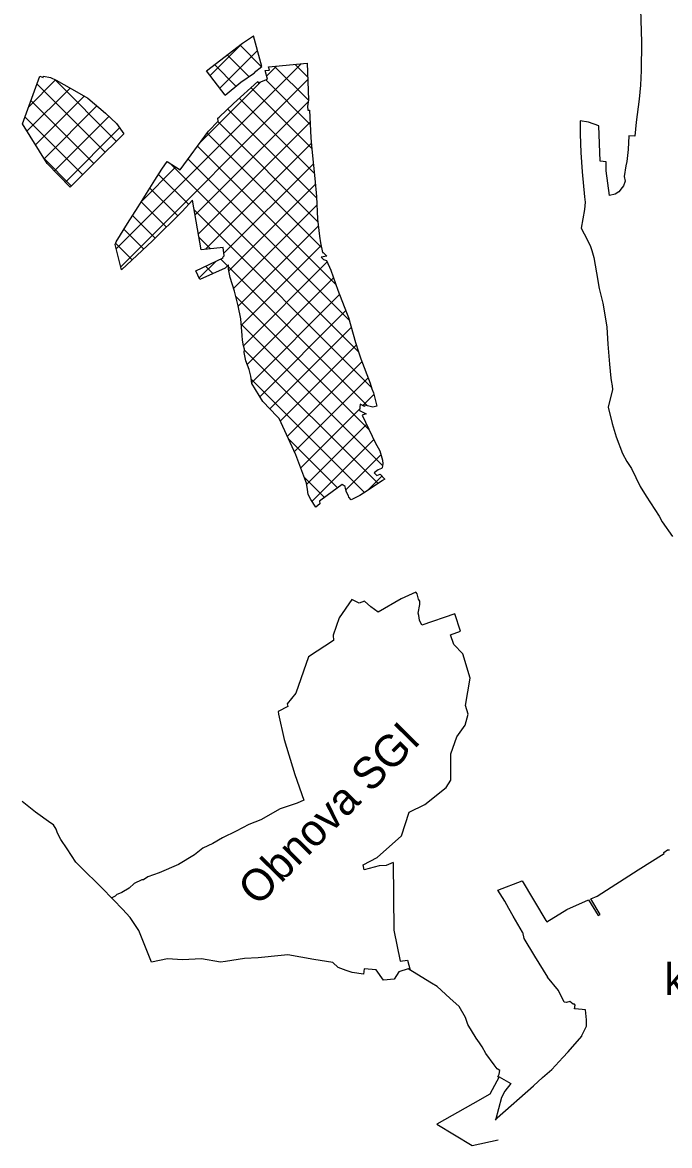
# Model space of a CAD drawing. Extents: x -550720 to -543671, y -1204329 to -1198338.
# Drawn here: x -547935 to -545892, y -1204329 to -1200786 of the extents above; entities that cross this region are included whole.
import ezdxf

# ---------------------------------------------------------------- set-up
doc = ezdxf.new("R2010")
doc.units = 0
for name, color, linetype in [('Ob šetřený', 7, 'Continuous'), ('obnova SGI', 7, 'Continuous'), ('Text kú', 7, 'Continuous'), ('šrafy', 7, 'Continuous')]:
    doc.layers.add(name, color=color, linetype=linetype)

msp = doc.modelspace()

# ---------------------------------------------------------------- linework, layer by layer
at = {"layer": 'Ob šetřený'}
for p, q in [((-545983.3, -1200744.3), (-545980.6, -1200848)), ((-547354, -1200938.3), (-547239.8, -1200851.8)), ((-547239.8, -1200851.8), (-547205.7, -1200827.7)), ((-547178.8, -1200925), (-547205.7, -1200827.7)), ((-545980.6, -1200848), (-545981.5, -1200937.8)), ((-547202.9, -1200943.6), (-547178.8, -1200925)), ((-547157.8, -1200926.2), (-547035.7, -1200914.4)), ((-547035.7, -1200914.4), (-547031.4, -1201029.9)), ((-547934.3, -1201106.2), (-547879.4, -1200955.7)), ((-547879.4, -1200955.7), (-547869.7, -1200960)), ((-547869.7, -1200960), (-547868.4, -1200955)), ((-547868.4, -1200955), (-547846.7, -1200959.7)), ((-547846.7, -1200959.7), (-547828.7, -1200967.9)), ((-547295.3, -1201015), (-547354, -1200938.3)), ((-547245.8, -1200974.7), (-547202.6, -1200944.7)), ((-547202.6, -1200944.7), (-547202.9, -1200943.6)), ((-547168.7, -1200937.3), (-547154.9, -1200936.1)), ((-547160.8, -1200965.4), (-547168.7, -1200937.3)), ((-547154.9, -1200936.1), (-547157.8, -1200926.2)), ((-545981.5, -1200937.8), (-545983.1, -1200984.2)), ((-547828.7, -1200967.9), (-547755.2, -1201009.3)), ((-547295.3, -1201015), (-547245.8, -1200974.7)), ((-547268.2, -1201041.3), (-547192, -1200971.8)), ((-547192, -1200971.8), (-547190.1, -1200976.5)), ((-547190.1, -1200976.5), (-547160.8, -1200965.4)), ((-545983.1, -1200984.2), (-545988, -1201028)), ((-547755.2, -1201009.3), (-547728.1, -1201025)), ((-547728.1, -1201025), (-547673, -1201071.9)), ((-547031.4, -1201029.9), (-547034.5, -1201051.6)), ((-545988, -1201028), (-545996.8, -1201100.7)), ((-547313.2, -1201084.3), (-547268.2, -1201041.3)), ((-547034.5, -1201051.6), (-547034.1, -1201062.9)), ((-547034.1, -1201062.9), (-547028.1, -1201062.4)), ((-547028.1, -1201062.4), (-547024.6, -1201149.7)), ((-547673, -1201071.9), (-547638.2, -1201105.1)), ((-547347.2, -1201129.3), (-547317.3, -1201097.1)), ((-547317.8, -1201087.9), (-547313.2, -1201084.3)), ((-547317.3, -1201097.1), (-547317.8, -1201087.9)), ((-546173.6, -1201096.4), (-546173.7, -1201138.4)), ((-546147.3, -1201100.8), (-546173.6, -1201096.4)), ((-546115.5, -1201111.9), (-546147.3, -1201100.8)), ((-545996.8, -1201100.7), (-546001.8, -1201144.2)), ((-547856.4, -1201231.4), (-547934.3, -1201106.2)), ((-547614.5, -1201136.8), (-547703.2, -1201224.6)), ((-547638.2, -1201105.1), (-547614.5, -1201136.8)), ((-547437.2, -1201251.1), (-547347.2, -1201129.3)), ((-546111.1, -1201223.8), (-546115.5, -1201111.9)), ((-547024.6, -1201149.7), (-547021, -1201186.1)), ((-546173.7, -1201138.4), (-546171.7, -1201196.6)), ((-546020.7, -1201143.8), (-546023, -1201187.1)), ((-546001.8, -1201144.2), (-546020.7, -1201143.8)), ((-547021, -1201186.1), (-547011.2, -1201277.8)), ((-546171.7, -1201196.6), (-546167.9, -1201257.2)), ((-546023, -1201187.1), (-546027, -1201224.9)), ((-547783.7, -1201305.8), (-547856.4, -1201231.4)), ((-547703.2, -1201224.6), (-547783.7, -1201305.8)), ((-547494.2, -1201248.5), (-547478.1, -1201224.7)), ((-547478.1, -1201224.7), (-547437.2, -1201251.1)), ((-546092.4, -1201225.8), (-546111.1, -1201223.8)), ((-546091.6, -1201253.6), (-546092.4, -1201225.8)), ((-546029.6, -1201238.4), (-546034.8, -1201271.5)), ((-546027, -1201224.9), (-546029.6, -1201238.4)), ((-547516.8, -1201283.4), (-547494.2, -1201248.5)), ((-547011.2, -1201277.8), (-547006.5, -1201335.2)), ((-546167.9, -1201257.2), (-546160.6, -1201335.9)), ((-546081.3, -1201331.6), (-546091.6, -1201253.6)), ((-546034.8, -1201271.5), (-546032, -1201286.6)), ((-547569.7, -1201367.4), (-547516.8, -1201283.4)), ((-546041.1, -1201306.9), (-546051.5, -1201320)), ((-546037.5, -1201300.9), (-546041.1, -1201306.9)), ((-546032, -1201286.6), (-546037.5, -1201300.9)), ((-547397.4, -1201346.4), (-547430.2, -1201382.5)), ((-547370.7, -1201503), (-547397.4, -1201346.4)), ((-547006.5, -1201335.2), (-547002.9, -1201406.5)), ((-546160.6, -1201335.9), (-546157.8, -1201353.1)), ((-546063.4, -1201327.6), (-546081.3, -1201331.6)), ((-546051.5, -1201320), (-546063.4, -1201327.6)), ((-547602.8, -1201419.8), (-547569.7, -1201367.4)), ((-547430.2, -1201382.5), (-547524.1, -1201475.3)), ((-546160.8, -1201376.4), (-546171, -1201435)), ((-546157.8, -1201353.1), (-546160.8, -1201376.4)), ((-547639.1, -1201478.2), (-547602.8, -1201419.8)), ((-547002.9, -1201406.5), (-546996.7, -1201460.6)), ((-546171, -1201435), (-546161.8, -1201452.8)), ((-546161.8, -1201452.8), (-546142, -1201490.1)), ((-547642.3, -1201485.9), (-547639.1, -1201478.2)), ((-547622.2, -1201566.6), (-547642.3, -1201485.9)), ((-547524.1, -1201475.3), (-547622.2, -1201566.6)), ((-546996.7, -1201460.6), (-546994.3, -1201481.4)), ((-546994.3, -1201481.4), (-546987.6, -1201511.9)), ((-546142, -1201490.1), (-546136.7, -1201505.5)), ((-547301.2, -1201495.9), (-547370.7, -1201503)), ((-547302.3, -1201526.2), (-547297.8, -1201522.6)), ((-547301.5, -1201528), (-547302.3, -1201526.2)), ((-547297.8, -1201522.6), (-547301.2, -1201495.9)), ((-546973.6, -1201523.6), (-546992, -1201526.1)), ((-546992, -1201526.1), (-546984, -1201533.9)), ((-546987.6, -1201511.9), (-546985.1, -1201511.6)), ((-546985.1, -1201511.6), (-546973.6, -1201523.6)), ((-546136.7, -1201505.5), (-546130.6, -1201527.1)), ((-546130.6, -1201527.1), (-546123, -1201575.9)), ((-547386.9, -1201569.9), (-547301.5, -1201528)), ((-547294.3, -1201561.4), (-547374.6, -1201596.4)), ((-547284.3, -1201550.5), (-547294.3, -1201561.4)), ((-547284.7, -1201564.4), (-547284.3, -1201550.5)), ((-546984, -1201533.9), (-546974.7, -1201537.2)), ((-546974.7, -1201537.2), (-546960.7, -1201567.7)), ((-547374.6, -1201596.4), (-547386.9, -1201569.9)), ((-547279.3, -1201590.3), (-547284.7, -1201564.4)), ((-547265.5, -1201633.4), (-547279.3, -1201590.3)), ((-546960.7, -1201567.7), (-546938.6, -1201630.7)), ((-546123, -1201575.9), (-546113.6, -1201625.4)), ((-547253.9, -1201679.5), (-547265.5, -1201633.4)), ((-546938.6, -1201630.7), (-546911.4, -1201701.3)), ((-546113.6, -1201625.4), (-546102.7, -1201671.6)), ((-547245.7, -1201720.7), (-547253.9, -1201679.5)), ((-546911.4, -1201701.3), (-546905.7, -1201716.6)), ((-546102.7, -1201671.6), (-546094.1, -1201720.6)), ((-547240.8, -1201774), (-547245.7, -1201720.7)), ((-546905.7, -1201716.6), (-546882.8, -1201795.3)), ((-546094.1, -1201720.6), (-546090.3, -1201746.7)), ((-547239.9, -1201788.3), (-547240.8, -1201774)), ((-546090.3, -1201746.7), (-546086.5, -1201801.1)), ((-547237.1, -1201806.5), (-547239.9, -1201788.3)), ((-547234.1, -1201816.5), (-547237.1, -1201806.5)), ((-546882.8, -1201795.3), (-546873.7, -1201824.6)), ((-546086.5, -1201801.1), (-546081.4, -1201864)), ((-547234.7, -1201827.2), (-547234.1, -1201816.5)), ((-547229.3, -1201853.4), (-547234.7, -1201827.2)), ((-546873.7, -1201824.6), (-546866.2, -1201847.2)), ((-547219.2, -1201880.6), (-547229.3, -1201853.4)), ((-547214.1, -1201901.7), (-547219.2, -1201880.6)), ((-546866.2, -1201847.2), (-546836.6, -1201923.6)), ((-546081.4, -1201864), (-546076.9, -1201908.3)), ((-547210.6, -1201925), (-547214.1, -1201901.7)), ((-546076.9, -1201908.3), (-546076.1, -1201915.6)), ((-546076.1, -1201915.6), (-546072.6, -1201931.9)), ((-547176.2, -1201981.8), (-547210.6, -1201925)), ((-546836.6, -1201923.6), (-546831.6, -1201941.6)), ((-546831.6, -1201941.6), (-546826.7, -1201954.5)), ((-546072.3, -1201943.8), (-546085.7, -1201999.3)), ((-546072.6, -1201931.9), (-546072.3, -1201943.8)), ((-547130.6, -1202029.1), (-547176.2, -1201981.8)), ((-546826.7, -1201954.5), (-546818.7, -1201983.9)), ((-546818.7, -1201983.9), (-546815.8, -1201996.2)), ((-546868.4, -1201990), (-546870.5, -1202009.9)), ((-546870.5, -1202009.9), (-546849.8, -1202020.9)), ((-546854.4, -1201997.6), (-546868.4, -1201990)), ((-546849.8, -1202020.9), (-546862.8, -1202024.3)), ((-546854, -1201992.9), (-546854.4, -1201997.6)), ((-546828.6, -1201999.4), (-546854, -1201992.9)), ((-546815.8, -1201996.2), (-546828.6, -1201999.4)), ((-546085.7, -1201999.3), (-546073, -1202051.3)), ((-547124.8, -1202035.2), (-547130.6, -1202029.1)), ((-547072.2, -1202150.2), (-547124.8, -1202035.2)), ((-546862.8, -1202024.3), (-546830.4, -1202091.4)), ((-546073, -1202051.3), (-546060.3, -1202093.6)), ((-546830.4, -1202091.4), (-546821.6, -1202110.7)), ((-546060.3, -1202093.6), (-546039.9, -1202145.8)), ((-546821.6, -1202110.7), (-546806.7, -1202136.8)), ((-547046.2, -1202217.2), (-547072.2, -1202150.2)), ((-546806.7, -1202136.8), (-546798.2, -1202166.8)), ((-546039.9, -1202145.8), (-546027.2, -1202171.2)), ((-546812.1, -1202197.7), (-546824.1, -1202206.6)), ((-546801.5, -1202193.4), (-546812.1, -1202197.7)), ((-546799.5, -1202191.1), (-546801.5, -1202193.4)), ((-546797.3, -1202178.6), (-546799.5, -1202191.1)), ((-546798.2, -1202166.8), (-546797.3, -1202178.6)), ((-546027.2, -1202171.2), (-546011.8, -1202193.5)), ((-546011.8, -1202193.5), (-545984.6, -1202249.3)), ((-547037.7, -1202239.5), (-547046.2, -1202217.2)), ((-546797.7, -1202231.1), (-546846.1, -1202263.2)), ((-546824.1, -1202206.6), (-546815.8, -1202214.9)), ((-546815.8, -1202214.9), (-546805.4, -1202210.6)), ((-546805.4, -1202210.6), (-546791.1, -1202226.7)), ((-546791.1, -1202226.7), (-546797.7, -1202231.1)), ((-547034.9, -1202259.3), (-547037.7, -1202239.5)), ((-547032.4, -1202275.4), (-547034.9, -1202259.3)), ((-546925.4, -1202244), (-546972.5, -1202277.7)), ((-546915.6, -1202250), (-546925.4, -1202244)), ((-546914.9, -1202255.9), (-546915.6, -1202250)), ((-546911.7, -1202267.7), (-546914.9, -1202255.9)), ((-546905.6, -1202278.9), (-546911.7, -1202267.7)), ((-546846.1, -1202263.2), (-546870, -1202277.8)), ((-545984.6, -1202249.3), (-545965.7, -1202280.5)), ((-547024.7, -1202290.4), (-547032.4, -1202275.4)), ((-547008.2, -1202315), (-547024.7, -1202290.4)), ((-546995.5, -1202305), (-547008.2, -1202315)), ((-546972.5, -1202277.7), (-546996.6, -1202296.4)), ((-546996.6, -1202296.4), (-546995.5, -1202305)), ((-546904.8, -1202283.9), (-546905.6, -1202278.9)), ((-546896.5, -1202291.4), (-546904.8, -1202283.9)), ((-546870, -1202277.8), (-546896.5, -1202291.4)), ((-545965.7, -1202280.5), (-545924.5, -1202342.9)), ((-545924.5, -1202342.9), (-545915.6, -1202361)), ((-545915.6, -1202361), (-545882.3, -1202408)), ((-547893.1, -1203276.8), (-547935.2, -1203243.5)), ((-547845, -1203311.5), (-547893.1, -1203276.8)), ((-547836.9, -1203317), (-547845, -1203311.5)), ((-547827.8, -1203330.8), (-547836.9, -1203317)), ((-547824.3, -1203343.3), (-547827.8, -1203330.8)), ((-547813.9, -1203363.5), (-547824.3, -1203343.3)), ((-547794, -1203393.1), (-547813.9, -1203363.5)), ((-547766.1, -1203434.8), (-547794, -1203393.1)), ((-545909.8, -1203404.7), (-545898.5, -1203395.6)), ((-545909.3, -1203407.6), (-545909.8, -1203404.7)), ((-545898.5, -1203395.6), (-545891.9, -1203396)), ((-547750.1, -1203450.6), (-547766.1, -1203434.8)), ((-545991.3, -1203459.5), (-545909.3, -1203407.6)), ((-547686.1, -1203514.1), (-547750.1, -1203450.6)), ((-546120.6, -1203542.4), (-545991.3, -1203459.5)), ((-546433.5, -1203523), (-546357.3, -1203493.6)), ((-546357.3, -1203493.6), (-546282.2, -1203619.3)), ((-547646.8, -1203553.2), (-547686.1, -1203514.1)), ((-546411.6, -1203558.3), (-546433.5, -1203523)), ((-546140.8, -1203550.3), (-546120.6, -1203542.4)), ((-547619.3, -1203583.3), (-547646.8, -1203553.2)), ((-546399.5, -1203581.5), (-546411.6, -1203558.3)), ((-546385.7, -1203605.2), (-546399.5, -1203581.5)), ((-546215.7, -1203583.9), (-546147.3, -1203553.2)), ((-546147.3, -1203553.2), (-546117.3, -1203603.3)), ((-546111.2, -1203599.7), (-546140.8, -1203550.3)), ((-547595, -1203609.7), (-547619.3, -1203583.3)), ((-547567.3, -1203649.9), (-547595, -1203609.7)), ((-546356, -1203656.2), (-546385.7, -1203605.2)), ((-546279.4, -1203623.5), (-546215.7, -1203583.9)), ((-546117.3, -1203603.3), (-546111.2, -1203599.7)), ((-547527.5, -1203749.9), (-547567.3, -1203649.9)), ((-546282.2, -1203619.3), (-546279.4, -1203623.5)), ((-546356, -1203656.2), (-546351.8, -1203676.1)), ((-546351.8, -1203676.1), (-546318.5, -1203730.9)), ((-547476.6, -1203740.3), (-547527.5, -1203749.9)), ((-547429.8, -1203742.5), (-547476.6, -1203740.3)), ((-547369.7, -1203739.6), (-547429.8, -1203742.5)), ((-547309.9, -1203750.6), (-547369.7, -1203739.6)), ((-547294.2, -1203747.9), (-547309.9, -1203750.6)), ((-547233.9, -1203738.4), (-547294.2, -1203747.9)), ((-547190.1, -1203736.3), (-547233.9, -1203738.4)), ((-547117.7, -1203728.8), (-547190.1, -1203736.3)), ((-547096.6, -1203727.3), (-547117.7, -1203728.8)), ((-547015.2, -1203741.7), (-547096.6, -1203727.3)), ((-546955, -1203751.2), (-547015.2, -1203741.7)), ((-546938, -1203767), (-546955, -1203751.2)), ((-546318.5, -1203730.9), (-546277.1, -1203798.1)), ((-546912.9, -1203776.6), (-546938, -1203767)), ((-546893.6, -1203782.8), (-546912.9, -1203776.6)), ((-546858.1, -1203787.9), (-546893.6, -1203782.8)), ((-546856, -1203771.5), (-546858.1, -1203787.9)), ((-546818.4, -1203774.8), (-546856, -1203771.5)), ((-546794.9, -1203806.7), (-546818.4, -1203774.8)), ((-546746.6, -1203780.7), (-546760.9, -1203803.7)), ((-546717.4, -1203771.5), (-546746.6, -1203780.7)), ((-546643.5, -1203816.1), (-546717.4, -1203771.5)), ((-546760.9, -1203803.7), (-546794.9, -1203806.7)), ((-546625.6, -1203827.5), (-546643.5, -1203816.1)), ((-546585.4, -1203863.6), (-546625.6, -1203827.5)), ((-546242, -1203839.2), (-546277.1, -1203798.1)), ((-546556.2, -1203890.1), (-546585.4, -1203863.6)), ((-546224.2, -1203876.4), (-546242, -1203839.2)), ((-546536.3, -1203925), (-546556.2, -1203890.1)), ((-546217.2, -1203877.4), (-546224.2, -1203876.4)), ((-546206.2, -1203874.4), (-546217.2, -1203877.4)), ((-546196.1, -1203882.7), (-546206.2, -1203874.4)), ((-546192.2, -1203882.9), (-546196.1, -1203882.7)), ((-546190, -1203886.2), (-546192.2, -1203882.9)), ((-546191.5, -1203897.4), (-546190, -1203886.2)), ((-546189.5, -1203897.5), (-546191.5, -1203897.4)), ((-546157.7, -1203900.4), (-546189.5, -1203897.5)), ((-546153.6, -1203932.1), (-546157.7, -1203900.4)), ((-546529.2, -1203947), (-546536.3, -1203925)), ((-546153.7, -1203951.8), (-546153.6, -1203932.1)), ((-546502.9, -1203990.3), (-546529.2, -1203947)), ((-546169.1, -1203981.5), (-546153.7, -1203951.8)), ((-546492.2, -1204004.9), (-546502.9, -1203990.3)), ((-546483.8, -1204017.4), (-546492.2, -1204004.9)), ((-546212, -1204033.3), (-546168.9, -1203984.2)), ((-546168.9, -1203984.2), (-546169.1, -1203981.5)), ((-546472.2, -1204037.9), (-546483.8, -1204017.4)), ((-546445.7, -1204074), (-546472.2, -1204037.9)), ((-546228.9, -1204051.4), (-546212, -1204033.3)), ((-546436.6, -1204086.4), (-546445.7, -1204074)), ((-546263.8, -1204088.9), (-546228.9, -1204051.4)), ((-546427.9, -1204091.6), (-546436.6, -1204086.4)), ((-546434.2, -1204111.8), (-546429.5, -1204103.4)), ((-546434.2, -1204111.8), (-546430.1, -1204111.8)), ((-546430.1, -1204111.8), (-546393.3, -1204133.5)), ((-546429.5, -1204103.4), (-546427.9, -1204091.6)), ((-546292.7, -1204114.6), (-546263.8, -1204088.9)), ((-546435.6, -1204241.6), (-546321.6, -1204140.3)), ((-546393.3, -1204133.5), (-546412.3, -1204157.7)), ((-546321.6, -1204140.3), (-546292.7, -1204114.6)), ((-546422, -1204177.4), (-546441.4, -1204248.3)), ((-546412.3, -1204157.7), (-546422, -1204177.4)), ((-546441.4, -1204248.3), (-546435.6, -1204241.6))]:
    msp.add_line(p, q, dxfattribs=at)
at = {"layer": 'obnova SGI'}
for p, q in [((-546692.5, -1202583.3), (-546738.8, -1202604.6)), ((-546688.9, -1202588.9), (-546692.5, -1202583.3)), ((-546684.4, -1202605.3), (-546688.9, -1202588.9)), ((-546894.7, -1202606.2), (-546935.3, -1202663.7)), ((-546871.4, -1202618.3), (-546894.7, -1202606.2)), ((-546854.5, -1202611.6), (-546871.4, -1202618.3)), ((-546835.1, -1202629.9), (-546854.5, -1202611.6)), ((-546738.8, -1202604.6), (-546811.6, -1202646.7)), ((-546685.5, -1202649.2), (-546679.8, -1202622.1)), ((-546679.7, -1202611.2), (-546684.4, -1202605.3)), ((-546679.8, -1202622.1), (-546679.7, -1202611.2)), ((-546811.6, -1202646.7), (-546835.1, -1202629.9)), ((-546683.6, -1202656.3), (-546685.5, -1202649.2)), ((-546681.6, -1202671.9), (-546683.6, -1202656.3)), ((-546569.9, -1202652), (-546673.7, -1202686.9)), ((-546552, -1202706.1), (-546569.9, -1202652)), ((-546935.3, -1202663.7), (-546953.6, -1202718.8)), ((-546673.7, -1202686.9), (-546681.6, -1202671.9)), ((-546953.6, -1202718.8), (-546953.1, -1202735.8)), ((-546583.8, -1202717.6), (-546552, -1202706.1)), ((-546572.6, -1202748.2), (-546583.8, -1202717.6)), ((-546953.1, -1202735.8), (-547031.4, -1202787.5)), ((-546544.4, -1202778.1), (-546572.6, -1202748.2)), ((-547031.4, -1202787.5), (-547071.2, -1202901.5)), ((-546521.4, -1202854.4), (-546544.4, -1202778.1)), ((-546536.4, -1202940.7), (-546521.4, -1202854.4)), ((-547071.2, -1202901.5), (-547099.3, -1202935.4)), ((-547097.1, -1202943.9), (-547127.1, -1202959.5)), ((-547099.3, -1202935.4), (-547097.1, -1202943.9)), ((-546527.7, -1202967.8), (-546536.4, -1202940.7)), ((-547127.1, -1202959.5), (-547126.2, -1202968)), ((-547126.2, -1202968), (-547108.4, -1203047.9)), ((-546537.5, -1203003.1), (-546527.7, -1202967.8)), ((-546562.9, -1203039.2), (-546537.5, -1203003.1)), ((-547108.4, -1203047.9), (-547075, -1203158.3)), ((-546582.6, -1203092.7), (-546562.9, -1203039.2)), ((-546581.9, -1203175.8), (-546582.6, -1203092.7)), ((-547075, -1203158.3), (-547046.8, -1203238.8)), ((-546596.8, -1203199.5), (-546581.9, -1203175.8)), ((-546664.8, -1203253.2), (-546596.8, -1203199.5)), ((-547067.9, -1203249.2), (-547121.3, -1203266.6)), ((-547046.8, -1203238.8), (-547067.9, -1203249.2)), ((-546714.1, -1203277.4), (-546664.8, -1203253.2)), ((-547121.3, -1203266.6), (-547182.3, -1203301.7)), ((-546738.4, -1203352.3), (-546714.1, -1203277.4)), ((-547220.2, -1203316.5), (-547259.8, -1203337.5)), ((-547182.3, -1203301.7), (-547220.2, -1203316.5)), ((-547303.2, -1203358.4), (-547334, -1203375.7)), ((-547259.8, -1203337.5), (-547303.2, -1203358.4)), ((-546815.1, -1203420.2), (-546738.4, -1203352.3)), ((-547365.8, -1203391.1), (-547391.2, -1203411.8)), ((-547334, -1203375.7), (-547365.8, -1203391.1)), ((-547391.2, -1203411.8), (-547442.4, -1203442.1)), ((-546859.4, -1203443.7), (-546815.1, -1203420.2)), ((-546764, -1203436.4), (-546786.4, -1203445.1)), ((-546764, -1203436.4), (-546761.8, -1203649.2)), ((-547503.1, -1203468.2), (-547539, -1203480.7)), ((-547442.4, -1203442.1), (-547503.1, -1203468.2)), ((-546856.3, -1203459.5), (-546859.4, -1203443.7)), ((-546809.1, -1203446.2), (-546856.3, -1203459.5)), ((-546786.4, -1203445.1), (-546809.1, -1203446.2)), ((-547581.9, -1203502), (-547598.3, -1203517.1)), ((-547558.2, -1203490.6), (-547581.9, -1203502)), ((-547552.3, -1203490.1), (-547558.2, -1203490.6)), ((-547539, -1203480.7), (-547552.3, -1203490.1)), ((-547641.8, -1203541.7), (-547652.5, -1203547.5)), ((-547636.4, -1203536.5), (-547641.8, -1203541.7)), ((-547628.3, -1203534), (-547636.4, -1203536.5)), ((-547620.7, -1203530.1), (-547628.3, -1203534)), ((-547598.3, -1203517.1), (-547620.7, -1203530.1)), ((-546761.8, -1203649.2), (-546742.8, -1203747)), ((-546742.8, -1203747), (-546718.7, -1203744)), ((-546718.7, -1203744), (-546710.5, -1203775.6))]:
    msp.add_line(p, q, dxfattribs=at)
at = {"layer": 'šrafy'}
for p, q in [((-547206.7, -1200828.4), (-547205, -1200830.1)), ((-547342.5, -1200953.4), (-547244.5, -1200855.4)), ((-547311.8, -1200993.4), (-547192.8, -1200874.4)), ((-547288.1, -1200888.4), (-547219.9, -1200956.7)), ((-547247.9, -1200858), (-547180, -1200925.9)), ((-547638.7, -1201500.4), (-547054.4, -1200916.2)), ((-547328.4, -1200918.9), (-547260.6, -1200986.7)), ((-547163.8, -1200954.9), (-547132.8, -1200923.8)), ((-547138.6, -1200924.4), (-547031.6, -1201031.4)), ((-547074.2, -1200918.1), (-547034.1, -1200958.2)), ((-547920.4, -1201128.6), (-547784.6, -1200992.8)), ((-547914.6, -1201052.1), (-547829.9, -1200967.4)), ((-547888.6, -1200980.9), (-547674, -1201195.6)), ((-547832.8, -1200966.1), (-547638.4, -1201160.4)), ((-547624.6, -1201557.1), (-547033.8, -1200966.3)), ((-547372.6, -1201163.6), (-547182.6, -1200973.7)), ((-547213.3, -1200991.2), (-547021.3, -1201183.1)), ((-547166.2, -1200967.5), (-547026.3, -1201107.4)), ((-547893.3, -1201172.2), (-547739.5, -1201018.4)), ((-547250.2, -1201024.9), (-547012.9, -1201262.3)), ((-547907.5, -1201032.8), (-547709.4, -1201230.8)), ((-547866.1, -1201215.8), (-547699.6, -1201049.2)), ((-547389.5, -1201392.7), (-547032.2, -1201035.4)), ((-547286.8, -1201059.1), (-547006.3, -1201339.6)), ((-547926.4, -1201084.6), (-547744.6, -1201266.4)), ((-547834, -1201254.3), (-547662, -1201082.4)), ((-547379.2, -1201453.2), (-547026.6, -1201100.5)), ((-547318.3, -1201098.2), (-547001.9, -1201414.7)), ((-547799.1, -1201290.1), (-547627.9, -1201118.9)), ((-547351.8, -1201135.5), (-546991.1, -1201496.2)), ((-547357, -1201501.6), (-547022.9, -1201167.5)), ((-547381.8, -1201176.2), (-546944.8, -1201613.2)), ((-547866.5, -1201215.2), (-547779.8, -1201301.9)), ((-547558.3, -1201349.4), (-547451.1, -1201242.1)), ((-547468.4, -1201231), (-546873.2, -1201826.2)), ((-547411.9, -1201216.8), (-546903.1, -1201725.6)), ((-547298.9, -1201514.2), (-547016.2, -1201231.5)), ((-547505, -1201265.1), (-547409.9, -1201360.2)), ((-547532.5, -1201308.3), (-547444.4, -1201396.5)), ((-547283.6, -1201569.6), (-547009.7, -1201295.8)), ((-547559.8, -1201351.7), (-547479.9, -1201431.6)), ((-547392, -1201378.1), (-546832.8, -1201937.3)), ((-547268.2, -1201625), (-547005.1, -1201361.9)), ((-547587.2, -1201395.1), (-547515.5, -1201466.8)), ((-547614.4, -1201438.5), (-547551.9, -1201501.1)), ((-547253.6, -1201681), (-547000.4, -1201427.9)), ((-547640.9, -1201482.7), (-547588.5, -1201535.2)), ((-547377.5, -1201463.3), (-547340.9, -1201499.9)), ((-547243.8, -1201741.9), (-546992.3, -1201490.5)), ((-547376.6, -1201592), (-547323.5, -1201538.8)), ((-547356.5, -1201555), (-547333.2, -1201578.4)), ((-547309.1, -1201531.7), (-547287.2, -1201553.6)), ((-547284.5, -1201556.4), (-546845.9, -1201995)), ((-547237.1, -1201806), (-546972.7, -1201541.6)), ((-547225.1, -1201864.7), (-546952.3, -1201591.9)), ((-547261.3, -1201650.3), (-546840, -1202071.5)), ((-547211.1, -1201921.4), (-546933.6, -1201643.9)), ((-547185.5, -1201966.5), (-546913.9, -1201694.9)), ((-547244.1, -1201738.1), (-546798.3, -1202184)), ((-547153.6, -1202005.3), (-546896.5, -1201748.2)), ((-547121, -1202043.5), (-546880.5, -1201802.9)), ((-547234.3, -1201818.7), (-546812.2, -1202240.8)), ((-547098.8, -1202092), (-546862.8, -1201856)), ((-547212.7, -1201911), (-546855, -1202268.6)), ((-547076.6, -1202140.5), (-546843.1, -1201906.9)), ((-546860, -1201994.6), (-546825.3, -1201959.8)), ((-547056.4, -1202190.9), (-546869.9, -1202004.5)), ((-547037.3, -1202242.5), (-546848.5, -1202053.8)), ((-547095.8, -1202098.6), (-546940, -1202254.4)), ((-547020.6, -1202296.6), (-546825.7, -1202101.7)), ((-546913.7, -1202260.4), (-546803, -1202149.7)), ((-547045.1, -1202220), (-546980.9, -1202284.2)), ((-546845.2, -1202262.6), (-546799.7, -1202217.1)), ((-546430.1, -1204111.8), (-546459.2, -1204166.7)), ((-546459.2, -1204166.7), (-546513.3, -1204197.3)), ((-546513.3, -1204197.3), (-546626.4, -1204261.2)), ((-546626.4, -1204261.2), (-546515.4, -1204328.8)), ((-546515.4, -1204328.8), (-546433.2, -1204310.6))]:
    msp.add_line(p, q, dxfattribs=at)

# ---------------------------------------------------------------- texts
at = {"layer": 'Text kú'}
msp.add_text('Obnova SGI', height=100, rotation=45.1793, dxfattribs=at).set_placement((-547192.1, -1203577.1))
msp.add_text('k.ú. Tavrožná Lhota-chatová oblast', height=100, dxfattribs=at).set_placement((-545907.9, -1203853.8))

doc.saveas('drawing.dxf')
